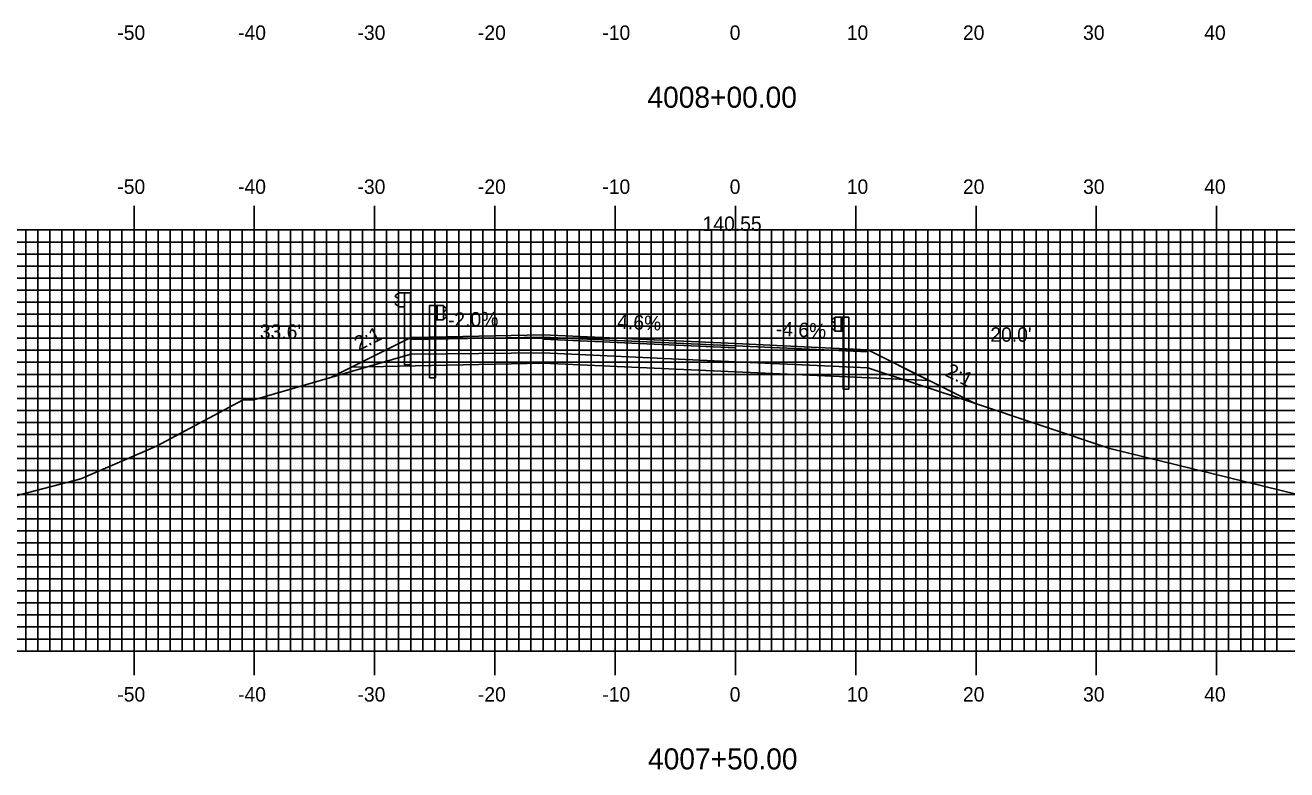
# Model space of a CAD drawing. Extents: x 851753 to 852097, y 364661 to 364881.
# Drawn here: x 851860.2 to 851965.1, y 364724.5 to 364786.4 of the extents above; entities that cross this region are included whole.
import ezdxf

# ---------------------------------------------------------------- set-up
doc = ezdxf.new("R2010")
doc.units = 0
for name, color, linetype in [('ANNOTATION', 7, 'Continuous'), ('D_Guardrail_Beam_Lt', 7, 'Continuous'), ('D_Guardrail_Beam_Rt', 7, 'Continuous'), ('D_Roadway_Centerline_Text', 7, 'Continuous'), ('D_Roadway_Edge_Shoulder', 7, 'Continuous'), ('D_Roadway_Edge_TW', 7, 'Continuous'), ('D_Roadway_Pavement', 7, 'Continuous'), ('D_Roadway_SlopeLines', 7, 'Continuous'), ('D_Roadway_SubGrade', 7, 'Continuous'), ('D_Text_Standard', 7, 'Continuous'), ('H_V ANNOTATION', 7, 'Continuous'), ('M_Guardrail', 7, 'Continuous'), ('M_Roadway_Centerline', 7, 'Continuous'), ('MAJOR', 7, 'Continuous'), ('MINOR', 7, 'Continuous'), ('S_Roadway_Centerline', 7, 'Continuous')]:
    doc.layers.add(name, color=color, linetype=linetype)

msp = doc.modelspace()

# ---------------------------------------------------------------- linework, layer by layer
at = {"layer": 'D_Guardrail_Beam_Lt'}
for p, q in [((851893.81, 364763.08), (851893.81, 364757.08)), ((851894.28, 364763.08), (851893.81, 364763.08)), ((851894.97, 364763.08), (851894.28, 364763.08)), ((851894.28, 364763.08), (851894.28, 364761.91)), ((851894.35, 364763.08), (851894.35, 364761.91)), ((851894.45, 364763.08), (851894.45, 364761.91)), ((851894.97, 364761.91), (851894.97, 364763.08)), ((851894.97, 364762.99), (851895.05, 364762.98)), ((851895.05, 364762.01), (851894.97, 364761.99)), ((851894.98, 364762.53), (851894.98, 364762.46)), ((851895.2, 364762.73), (851895.01, 364762.59)), ((851895.01, 364762.39), (851895.2, 364762.26)), ((851895.06, 364762.97), (851895.2, 364762.87)), ((851895.2, 364762.11), (851895.06, 364762.01)), ((851894.28, 364761.91), (851894.97, 364761.91)), ((851894.3, 364757.08), (851894.3, 364761.91)), ((851894.3, 364757.08), (851893.81, 364757.08))]:
    msp.add_line(p, q, dxfattribs=at)
for centre, major_axis, start_param, end_param in [((851895.04, 364762.94), (0.0417, 0), 0.959931, 1.376053), ((851895.05, 364762.53), (-0.0789, 0), 5.323254, 6.283185), ((851895.05, 364762.46), (-0.0789, 0), 6.283185, 7.243116), ((851895.04, 364762.05), (0.0417, 0), 4.907132, 5.323254), ((851895.15, 364762.8), (0.0877, 0), 5.323254, 7.243116), ((851895.15, 364762.19), (0.0877, 0), 5.323254, 7.243116)]:
    msp.add_ellipse(centre, major_axis=major_axis, ratio=0.995501, start_param=start_param, end_param=end_param, dxfattribs=at)
at = {"layer": 'D_Guardrail_Beam_Rt'}
for p, q in [((851927.42, 364762.03), (851927.28, 364761.93)), ((851927.51, 364762.05), (851927.44, 364762.03)), ((851927.51, 364762.13), (851928.2, 364762.13)), ((851927.51, 364760.97), (851927.51, 364762.13)), ((851928.03, 364762.13), (851928.03, 364760.97)), ((851928.14, 364762.13), (851928.14, 364760.97)), ((851928.2, 364762.13), (851928.67, 364762.13)), ((851928.2, 364762.13), (851928.2, 364760.97)), ((851928.67, 364762.13), (851928.67, 364756.13)), ((851927.28, 364761.78), (851927.47, 364761.65)), ((851927.47, 364761.45), (851927.28, 364761.31)), ((851927.28, 364761.17), (851927.42, 364761.07)), ((851927.44, 364761.06), (851927.51, 364761.05)), ((851927.51, 364761.58), (851927.51, 364761.51)), ((851928.2, 364760.97), (851927.51, 364760.97)), ((851928.18, 364756.13), (851928.18, 364760.97)), ((851928.18, 364756.13), (851928.67, 364756.13))]:
    msp.add_line(p, q, dxfattribs=at)
for centre, major_axis, start_param, end_param in [((851927.33, 364761.86), (-0.0877, 0), 5.323254, 7.243116), ((851927.45, 364761.99), (-0.0417, 0), 4.907132, 5.323254), ((851927.33, 364761.24), (-0.0877, 0), 5.323254, 7.243116), ((851927.45, 364761.1), (-0.0417, 0), 0.959931, 1.376053), ((851927.43, 364761.58), (0.0789, 0), 0, 0.959931), ((851927.43, 364761.51), (0.0789, 0), 5.323254, 6.283185)]:
    msp.add_ellipse(centre, major_axis=major_axis, ratio=0.995501, start_param=start_param, end_param=end_param, dxfattribs=at)
at = {"layer": 'D_Roadway_Edge_Shoulder'}
for points in [[(851903.24, 364760.65), (851895.24, 364760.49), (851895.24, 364760.49), (851892.24, 364760.43), (851892.24, 364760.27), (851903.24, 364760.46)], [(851919.24, 364759.92), (851927.24, 364759.55), (851927.24, 364759.55), (851930.24, 364759.41), (851930.24, 364759.24), (851919.24, 364759.75)]]:
    msp.add_lwpolyline(points, close=True, dxfattribs=at)
at = {"layer": 'D_Roadway_Edge_TW'}
msp.add_lwpolyline([(851903.24, 364760.65), (851919.24, 364759.92), (851919.24, 364759.75), (851903.24, 364760.46)], close=True, dxfattribs=at)
at = {"layer": 'D_Roadway_Pavement'}
msp.add_lwpolyline([(851903.24, 364760.46), (851919.24, 364759.75), (851919.24, 364759.58), (851903.24, 364760.29)], close=True, dxfattribs=at)
for points in [[(851903.24, 364760.46), (851903.24, 364760.29)], [(851919.24, 364759.75), (851919.24, 364759.58)], [(851919.24, 364759.75), (851919.24, 364759.58)], [(851919.24, 364759.75), (851919.24, 364759.58)]]:
    msp.add_lwpolyline(points, dxfattribs=at)
at = {"layer": 'D_Roadway_SlopeLines'}
msp.add_line((851892.24, 364760.43), (851885.61, 364757.11), dxfattribs=at)
for points in [[(851892.24, 364760.43), (851890.21, 364759.42)], [(851930.24, 364759.41), (851939.21, 364754.93)]]:
    msp.add_lwpolyline(points, dxfattribs=at)
at = {"layer": 'D_Roadway_SubGrade'}
for points in [[(851903.24, 364760.29), (851903.24, 364760.46), (851892.24, 364760.27), (851892.24, 364760.43), (851887.33, 364757.98), (851903.24, 364758.29)], [(851903.24, 364760.29), (851919.24, 364759.58), (851919.24, 364757.58), (851903.24, 364758.29)], [(851919.24, 364759.58), (851919.24, 364759.75), (851930.24, 364759.24), (851930.24, 364759.41), (851935.32, 364756.87), (851919.24, 364757.58)]]:
    msp.add_lwpolyline(points, close=True, dxfattribs=at)
at = {"layer": 'M_Guardrail'}
for p, q in [((851891.14, 364764.06), (851891, 364763.96)), ((851891.24, 364764.08), (851891.16, 364764.07)), ((851891.24, 364764.15), (851891.73, 364764.15)), ((851891.24, 364762.99), (851891.24, 364764.15)), ((851891.73, 364764.15), (851892.22, 364764.15)), ((851891.73, 364764.15), (851891.73, 364762.99)), ((851892.22, 364764.15), (851892.22, 364758.15)), ((851891, 364763.82), (851891.19, 364763.68)), ((851891.19, 364763.46), (851891, 364763.33)), ((851891, 364763.18), (851891.14, 364763.08)), ((851891.16, 364763.08), (851891.24, 364763.06)), ((851891.22, 364763.62), (851891.22, 364763.53)), ((851891.73, 364762.99), (851891.24, 364762.99)), ((851891.73, 364758.15), (851891.73, 364762.99)), ((851891.73, 364758.15), (851892.22, 364758.15))]:
    msp.add_line(p, q, dxfattribs=at)
for centre, major_axis, start_param, end_param in [((851891.16, 364764.03), (-0.0417, 0), 4.886922, 5.323254), ((851891.05, 364763.89), (-0.0877, 0), 5.323254, 7.243116), ((851891.05, 364763.25), (-0.0877, 0), 5.323254, 7.243116), ((851891.16, 364763.12), (-0.0417, 0), 0.959931, 1.396263), ((851891.15, 364763.62), (0.0789, 0), 0, 0.959931), ((851891.15, 364763.53), (0.0789, 0), 5.323254, 6.283185)]:
    msp.add_ellipse(centre, major_axis=major_axis, ratio=0.995501, start_param=start_param, end_param=end_param, dxfattribs=at)
at = {"layer": 'MAJOR'}
for p, q in [((851869.24, 364771.37), (851869.24, 364769.37)), ((851879.24, 364771.37), (851879.24, 364769.37)), ((851889.24, 364771.37), (851889.24, 364769.37)), ((851899.24, 364771.37), (851899.24, 364769.37)), ((851909.24, 364771.37), (851909.24, 364769.37)), ((851919.24, 364771.37), (851919.24, 364769.37)), ((851929.24, 364771.37), (851929.24, 364769.37)), ((851939.24, 364771.37), (851939.24, 364769.37)), ((851949.24, 364771.37), (851949.24, 364769.37)), ((851959.24, 364771.37), (851959.24, 364769.37)), ((851779.24, 364769.37), (852059.24, 364769.37)), ((851779.24, 364769.37), (852059.24, 364769.37)), ((851869.24, 364734.37), (851869.24, 364769.37)), ((851879.24, 364734.37), (851879.24, 364769.37)), ((851889.24, 364734.37), (851889.24, 364769.37)), ((851899.24, 364734.37), (851899.24, 364769.37)), ((851909.24, 364734.37), (851909.24, 364769.37)), ((851919.24, 364734.37), (851919.24, 364769.37)), ((851929.24, 364734.37), (851929.24, 364769.37)), ((851939.24, 364734.37), (851939.24, 364769.37)), ((851949.24, 364734.37), (851949.24, 364769.37)), ((851959.24, 364734.37), (851959.24, 364769.37)), ((851779.24, 364764.37), (852059.24, 364764.37)), ((851779.24, 364759.37), (852059.24, 364759.37)), ((851779.24, 364754.37), (852059.24, 364754.37)), ((851779.24, 364749.37), (852059.24, 364749.37)), ((851779.24, 364744.37), (852059.24, 364744.37)), ((851779.24, 364739.37), (852059.24, 364739.37)), ((851779.24, 364734.37), (852059.24, 364734.37)), ((851779.24, 364734.37), (852059.24, 364734.37)), ((851869.24, 364732.37), (851869.24, 364734.37)), ((851879.24, 364732.37), (851879.24, 364734.37)), ((851889.24, 364732.37), (851889.24, 364734.37)), ((851899.24, 364732.37), (851899.24, 364734.37)), ((851909.24, 364732.37), (851909.24, 364734.37)), ((851919.24, 364732.37), (851919.24, 364734.37)), ((851929.24, 364732.37), (851929.24, 364734.37)), ((851939.24, 364732.37), (851939.24, 364734.37)), ((851949.24, 364732.37), (851949.24, 364734.37)), ((851959.24, 364732.37), (851959.24, 364734.37))]:
    msp.add_line(p, q, dxfattribs=at)
at = {"layer": 'MINOR'}
for p, q in [((851860.24, 364734.37), (851860.24, 364769.37)), ((851861.24, 364734.37), (851861.24, 364769.37)), ((851862.24, 364734.37), (851862.24, 364769.37)), ((851863.24, 364734.37), (851863.24, 364769.37)), ((851864.24, 364734.37), (851864.24, 364769.37)), ((851865.24, 364734.37), (851865.24, 364769.37)), ((851866.24, 364734.37), (851866.24, 364769.37)), ((851867.24, 364734.37), (851867.24, 364769.37)), ((851868.24, 364734.37), (851868.24, 364769.37)), ((851870.24, 364734.37), (851870.24, 364769.37)), ((851871.24, 364734.37), (851871.24, 364769.37)), ((851872.24, 364734.37), (851872.24, 364769.37)), ((851873.24, 364734.37), (851873.24, 364769.37)), ((851874.24, 364734.37), (851874.24, 364769.37)), ((851875.24, 364734.37), (851875.24, 364769.37)), ((851876.24, 364734.37), (851876.24, 364769.37)), ((851877.24, 364734.37), (851877.24, 364769.37)), ((851878.24, 364734.37), (851878.24, 364769.37)), ((851880.24, 364734.37), (851880.24, 364769.37)), ((851881.24, 364734.37), (851881.24, 364769.37)), ((851882.24, 364734.37), (851882.24, 364769.37)), ((851883.24, 364734.37), (851883.24, 364769.37)), ((851884.24, 364734.37), (851884.24, 364769.37)), ((851885.24, 364734.37), (851885.24, 364769.37)), ((851886.24, 364734.37), (851886.24, 364769.37)), ((851887.24, 364734.37), (851887.24, 364769.37)), ((851888.24, 364734.37), (851888.24, 364769.37)), ((851890.24, 364734.37), (851890.24, 364769.37)), ((851891.24, 364734.37), (851891.24, 364769.37)), ((851892.24, 364734.37), (851892.24, 364769.37)), ((851893.24, 364734.37), (851893.24, 364769.37)), ((851894.24, 364734.37), (851894.24, 364769.37)), ((851895.24, 364734.37), (851895.24, 364769.37)), ((851896.24, 364734.37), (851896.24, 364769.37)), ((851897.24, 364734.37), (851897.24, 364769.37)), ((851898.24, 364734.37), (851898.24, 364769.37)), ((851900.24, 364734.37), (851900.24, 364769.37)), ((851901.24, 364734.37), (851901.24, 364769.37)), ((851902.24, 364734.37), (851902.24, 364769.37)), ((851903.24, 364734.37), (851903.24, 364769.37)), ((851904.24, 364734.37), (851904.24, 364769.37)), ((851905.24, 364734.37), (851905.24, 364769.37)), ((851906.24, 364734.37), (851906.24, 364769.37)), ((851907.24, 364734.37), (851907.24, 364769.37)), ((851908.24, 364734.37), (851908.24, 364769.37)), ((851910.24, 364734.37), (851910.24, 364769.37)), ((851911.24, 364734.37), (851911.24, 364769.37)), ((851912.24, 364734.37), (851912.24, 364769.37)), ((851913.24, 364734.37), (851913.24, 364769.37)), ((851914.24, 364734.37), (851914.24, 364769.37)), ((851915.24, 364734.37), (851915.24, 364769.37)), ((851916.24, 364734.37), (851916.24, 364769.37)), ((851917.24, 364734.37), (851917.24, 364769.37)), ((851918.24, 364734.37), (851918.24, 364769.37)), ((851920.24, 364734.37), (851920.24, 364769.37)), ((851921.24, 364734.37), (851921.24, 364769.37)), ((851922.24, 364734.37), (851922.24, 364769.37)), ((851923.24, 364734.37), (851923.24, 364769.37)), ((851924.24, 364734.37), (851924.24, 364769.37)), ((851925.24, 364734.37), (851925.24, 364769.37)), ((851926.24, 364734.37), (851926.24, 364769.37)), ((851927.24, 364734.37), (851927.24, 364769.37)), ((851928.24, 364734.37), (851928.24, 364769.37)), ((851930.24, 364734.37), (851930.24, 364769.37)), ((851931.24, 364734.37), (851931.24, 364769.37)), ((851932.24, 364734.37), (851932.24, 364769.37)), ((851933.24, 364734.37), (851933.24, 364769.37)), ((851934.24, 364734.37), (851934.24, 364769.37)), ((851935.24, 364734.37), (851935.24, 364769.37)), ((851936.24, 364734.37), (851936.24, 364769.37)), ((851937.24, 364734.37), (851937.24, 364769.37)), ((851938.24, 364734.37), (851938.24, 364769.37)), ((851940.24, 364734.37), (851940.24, 364769.37)), ((851941.24, 364734.37), (851941.24, 364769.37)), ((851942.24, 364734.37), (851942.24, 364769.37)), ((851943.24, 364734.37), (851943.24, 364769.37)), ((851944.24, 364734.37), (851944.24, 364769.37)), ((851945.24, 364734.37), (851945.24, 364769.37)), ((851946.24, 364734.37), (851946.24, 364769.37)), ((851947.24, 364734.37), (851947.24, 364769.37)), ((851948.24, 364734.37), (851948.24, 364769.37)), ((851950.24, 364734.37), (851950.24, 364769.37)), ((851951.24, 364734.37), (851951.24, 364769.37)), ((851952.24, 364734.37), (851952.24, 364769.37)), ((851953.24, 364734.37), (851953.24, 364769.37)), ((851954.24, 364734.37), (851954.24, 364769.37)), ((851955.24, 364734.37), (851955.24, 364769.37)), ((851956.24, 364734.37), (851956.24, 364769.37)), ((851957.24, 364734.37), (851957.24, 364769.37)), ((851958.24, 364734.37), (851958.24, 364769.37)), ((851960.24, 364734.37), (851960.24, 364769.37)), ((851961.24, 364734.37), (851961.24, 364769.37)), ((851962.24, 364734.37), (851962.24, 364769.37)), ((851963.24, 364734.37), (851963.24, 364769.37)), ((851964.24, 364734.37), (851964.24, 364769.37)), ((851779.24, 364768.37), (852059.24, 364768.37)), ((851779.24, 364767.37), (852059.24, 364767.37)), ((851779.24, 364766.37), (852059.24, 364766.37)), ((851779.24, 364765.37), (852059.24, 364765.37)), ((851779.24, 364763.37), (852059.24, 364763.37)), ((851779.24, 364762.37), (852059.24, 364762.37)), ((851779.24, 364761.37), (852059.24, 364761.37)), ((851779.24, 364760.37), (852059.24, 364760.37)), ((851779.24, 364758.37), (852059.24, 364758.37)), ((851779.24, 364757.37), (852059.24, 364757.37)), ((851779.24, 364756.37), (852059.24, 364756.37)), ((851779.24, 364755.37), (852059.24, 364755.37)), ((851779.24, 364753.37), (852059.24, 364753.37)), ((851779.24, 364752.37), (852059.24, 364752.37)), ((851779.24, 364751.37), (852059.24, 364751.37)), ((851779.24, 364750.37), (852059.24, 364750.37)), ((851779.24, 364748.37), (852059.24, 364748.37)), ((851779.24, 364747.37), (852059.24, 364747.37)), ((851779.24, 364746.37), (852059.24, 364746.37)), ((851779.24, 364745.37), (852059.24, 364745.37)), ((851779.24, 364743.37), (852059.24, 364743.37)), ((851779.24, 364742.37), (852059.24, 364742.37)), ((851779.24, 364741.37), (852059.24, 364741.37)), ((851779.24, 364740.37), (852059.24, 364740.37)), ((851779.24, 364738.37), (852059.24, 364738.37)), ((851779.24, 364737.37), (852059.24, 364737.37)), ((851779.24, 364736.37), (852059.24, 364736.37)), ((851779.24, 364735.37), (852059.24, 364735.37))]:
    msp.add_line(p, q, dxfattribs=at)
at = {"layer": 'S_Roadway_Centerline'}
for points in [[(851878.27, 364755.23), (851879.2, 364755.25), (851882.63, 364756.25), (851892.24, 364759.05), (851895.24, 364759.08), (851903.24, 364759.16), (851919.24, 364758.42), (851927.24, 364758.05), (851930.24, 364757.92), (851938.94, 364755.02), (851950.37, 364751.21)], [(851779.24, 364740.33), (851785.18, 364741.78), (851793.93, 364742.23), (851798.31, 364742.64), (851809.09, 364743), (851811.88, 364743.09), (851814.16, 364743.17), (851829.74, 364743.49), (851845.53, 364744.07), (851846.88, 364744.13), (851847.38, 364744.15), (851864.82, 364748.68), (851871.1, 364751.41), (851878.27, 364755.23)], [(851950.37, 364751.21), (851968.79, 364746.7), (851973.85, 364745.71), (851977.69, 364745.58), (851991.46, 364744.81), (852007.78, 364745.28), (852009.57, 364745.32), (852010.8, 364745.36), (852022.36, 364745.73), (852027.69, 364745.64), (852031.99, 364745.46), (852034.87, 364745.34), (852035.13, 364745.39), (852044.9, 364746.3), (852049.13, 364746.6), (852059.24, 364747.43)]]:
    msp.add_lwpolyline(points, dxfattribs=at)

# ---------------------------------------------------------------- texts
at = {"layer": 'ANNOTATION'}
for s, rotation, p in [('-2.0%', 1.1458, (851895.35, 364761.3)), ('4.6%', 357.3663, (851909.39, 364761.17)), ('2:1', 26.5651, (851887.93, 364759.31)), ('-4.6%', 357.3663, (851922.57, 364760.57)), ('2:1', 333.4349, (851936.6, 364757.27))]:
    msp.add_text(s, height=1.2, rotation=rotation, dxfattribs=at).set_placement(p)
at = {"layer": 'D_Roadway_Centerline_Text'}
msp.add_text('140.55', height=1.2, dxfattribs=at).set_placement((851916.51, 364769.29))
at = {"layer": 'D_Text_Standard'}
for s, p in [("33.6'", (851879.7, 364760.32)), ("20.0'", (851940.43, 364760.08))]:
    msp.add_text(s, height=1.2, dxfattribs=at).set_placement(p)
at = {"layer": 'H_V ANNOTATION'}
for s, height, p in [('-50', 1.2, (851867.85, 364785.17)), ('-40', 1.2, (851877.89, 364785.17)), ('-30', 1.2, (851887.82, 364785.17)), ('-20', 1.2, (851897.83, 364785.17)), ('-10', 1.2, (851908.17, 364785.17)), ('0', 1.2, (851918.76, 364785.17)), ('10', 1.2, (851928.49, 364785.17)), ('20', 1.2, (851938.15, 364785.17)), ('30', 1.2, (851948.14, 364785.17)), ('40', 1.2, (851958.21, 364785.17)), ('4008+00.00', 1.75, (851911.92, 364779.53)), ('-50', 1.2, (851867.85, 364772.37)), ('-40', 1.2, (851877.89, 364772.37)), ('-30', 1.2, (851887.82, 364772.37)), ('-20', 1.2, (851897.83, 364772.37)), ('-10', 1.2, (851908.17, 364772.37)), ('0', 1.2, (851918.76, 364772.37)), ('10', 1.2, (851928.49, 364772.37)), ('20', 1.2, (851938.15, 364772.37)), ('30', 1.2, (851948.14, 364772.37)), ('40', 1.2, (851958.21, 364772.37)), ('-50', 1.2, (851867.85, 364730.17)), ('-40', 1.2, (851877.89, 364730.17)), ('-30', 1.2, (851887.82, 364730.17)), ('-20', 1.2, (851897.83, 364730.17)), ('-10', 1.2, (851908.17, 364730.17)), ('0', 1.2, (851918.76, 364730.17)), ('10', 1.2, (851928.49, 364730.17)), ('20', 1.2, (851938.15, 364730.17)), ('30', 1.2, (851948.14, 364730.17)), ('40', 1.2, (851958.21, 364730.17)), ('4007+50.00', 1.75, (851911.97, 364724.53))]:
    msp.add_text(s, height=height, dxfattribs=at).set_placement(p)
at = {"layer": 'M_Roadway_Centerline'}
for s, p in [('C', (851905.74, 364759.04)), ('L', (851905.75, 364759.03))]:
    msp.add_text(s, height=0.0146, dxfattribs=at).set_placement(p)

doc.saveas('drawing.dxf')
